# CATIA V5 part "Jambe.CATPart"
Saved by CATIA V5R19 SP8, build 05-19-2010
Part number: Jambe
Bounding box of the stored display mesh (mm): x -175 to 87.5, y -424.969 to 175, z -1974.802 to 2750
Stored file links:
  C:\Users\rcousturie\Desktop\EU_thinkMotion\iao\IAO_MMS_Groupe1\flacan\flacan\flacan\Jambe.CATPart
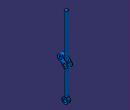
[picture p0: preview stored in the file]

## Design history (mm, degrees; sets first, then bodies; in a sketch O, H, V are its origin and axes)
Parameters
  `Longueur de jambe haute` = 1800 mm
Body1 (main body)
  Point1: (0, 0, -1800 {= -`Longueur de jambe haute`})
  Sketch1 on xy-plane, origin (0, 0, 0), H (1, 0, 0), V (0, 1, 0)
    circle A1 centre (0, 0) radius 87.5
    radius A1 = 87.5
  Pad1: profile Sketch1, direction (0, 0, 1), length 2750, opposite side length 1800 {= `Longueur de jambe haute`}
  Sketch2 on yz-plane, origin (0, 0, 0), H (0, 1, 0), V (0, 0, 1)
    arc A1 centre (0, 0) radius 175 from (-175, 0) to (123.7437, 123.7437) ccw
    point P1 (0, 0)
    arc A2 centre (-250, 250) radius 175 from (-126.2563, 373.7437) to (-250, 75) ccw
    point P2 (-250, 250)
    line L1 (123.7437, 123.7437) -> (-126.2563, 373.7437)
    point P5 (-175, 0)
    point P6 (-250, 75)
    connectcurve C1
    radius A2 = 175
    radius A1 = 175
    distance P1 O = 0
    distance P2 V = 250
    distance P2 H = 250
    distance P5 H = 0
    distance P6 V = 250
    tangency: L1 A1, L1 A2
  Pad2: profile Sketch2, direction (1, 0, 0), length 87.5, opposite side length 175
  Sketch3 on yz-plane, origin (0, 0, 0), H (0, 1, 0), V (0, 0, 1)
    circle A1 centre (0, -1800) radius 175
    point P1 (0, -1800)
    reference projected point E1 (0, -1800) from Point1
    radius A1 = 175
    distance P1 E1 = 0
  Pad3: profile Sketch3, direction (1, 0, 0), length 87.5, opposite side length 87.5
  Sketch4 on end face of Pad3, origin (87.5, 0, 0), H (0, 1, 0), V (0, 0, 1)
    circle A1 centre (0, -1800) radius 87.5
    point P1 (0, -1800)
    reference projected point E1 (0, -1800) from Point1
    radius A1 = 87.5
    distance P1 E1 = 0
  Pocket1: profile Sketch4, direction (-1, 0, 0), through (limit type 6)
  Sketch5 on face of Pad2, origin (87.5, 0, 0), H (0, 1, 0), V (0, 0, 1)
    circle A1 centre (0, 0) radius 87.5
    circle A2 centre (-250, 250) radius 87.5
    point P1 (-250, 250)
    radius A2 = 87.5
    radius A1 = 87.5
    distance P1 V = 250
    distance P1 H = 250
  Pocket2: profile Sketch5, direction (-1, 0, 0), through (limit type 6)
  Point2: (0, 0, 0)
